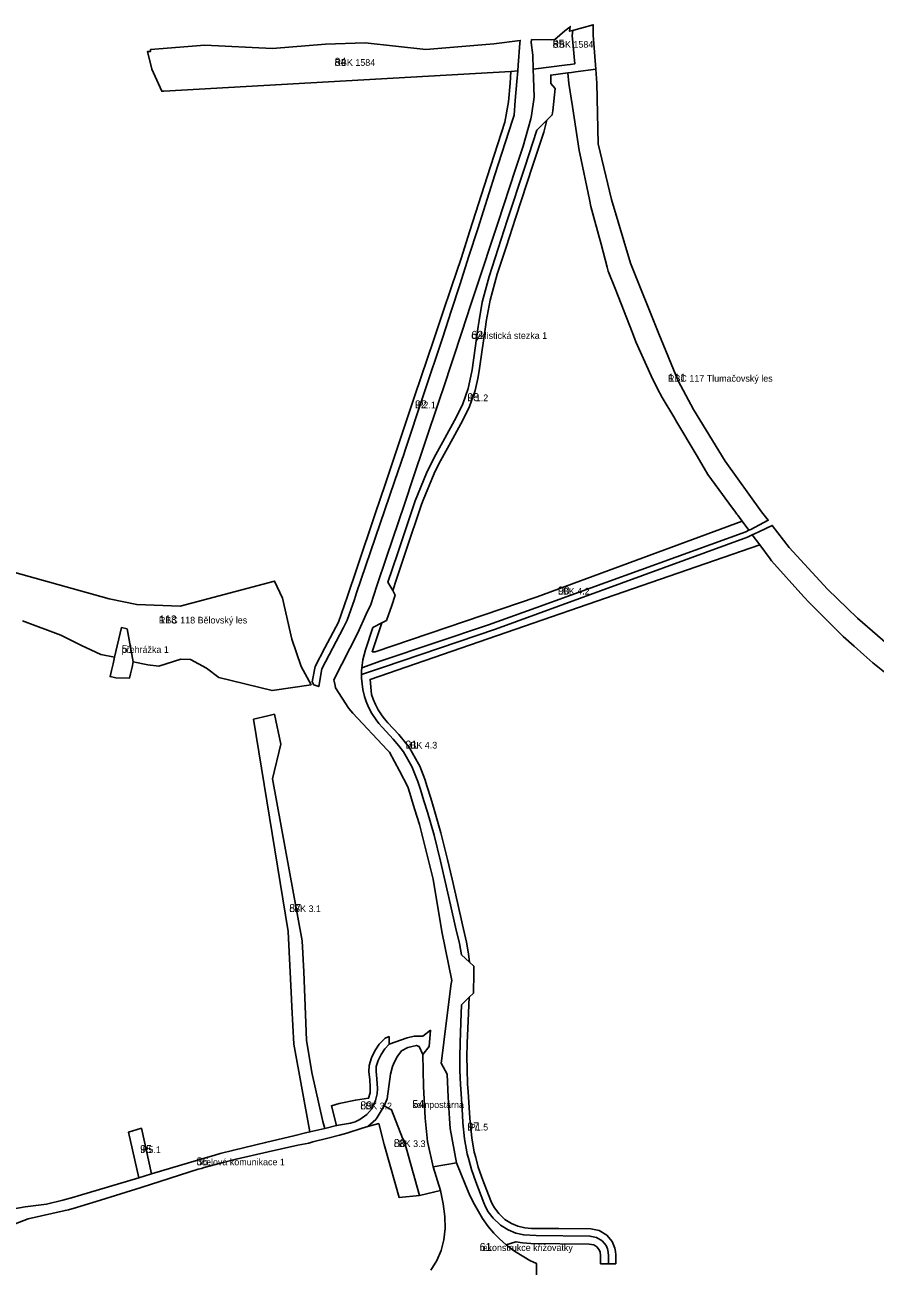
# Model space of a CAD drawing. Extents: x -535270 to -532834, y -1165802 to -1163869.
# Drawn here: x -534261 to -533624, y -1164800 to -1163869 of the extents above; entities that cross this region are included whole.
import ezdxf

# ---------------------------------------------------------------- set-up
doc = ezdxf.new("R2010")
doc.units = 0
for name, color, linetype in [('96120023', 7, 'Continuous'), ('96140023', 7, 'Continuous'), ('ID_VPO', 7, 'Continuous'), ('ID_VPS', 7, 'Continuous')]:
    doc.layers.add(name, color=color, linetype=linetype)

msp = doc.modelspace()

# ---------------------------------------------------------------- linework, layer by layer
at = {"layer": '96120023'}
for points in [[(-533865.57, -1163933.56), (-533865.91, -1163936.5), (-533870.02, -1163940.58), (-533877.5, -1163948), (-533886.52, -1163975.58), (-533899.61, -1164015.61), (-533906.48, -1164036.62), (-533913.28, -1164057.68), (-533918.33, -1164076.95), (-533920.79, -1164090.56), (-533921.44, -1164095.24), (-533925.9, -1164127.57), (-533927.65, -1164135.96), (-533928.81, -1164141.55), (-533932.87, -1164153.05), (-533937.61, -1164162.79), (-533947.95, -1164181.5), (-533954.46, -1164193.28), (-533960.24, -1164204.99), (-533968.74, -1164225.79), (-533982.01, -1164265.49), (-533989.08, -1164286.72), (-533985.51, -1164293.11), (-533983.62, -1164296.49), (-533986.25, -1164304.27), (-533990.03, -1164315.44), (-533993.55, -1164317.25), (-534000.42, -1164320.8), (-534005.96, -1164337.46), (-534007.91, -1164344.99), (-534008.51, -1164350.98), (-534008.75, -1164353.35), (-534008.78, -1164356.1), (-534008.8, -1164358.71), (-534007.78, -1164367.31), (-534006.52, -1164372.41), (-534005.28, -1164376.27), (-534003.55, -1164380.41), (-534001.01, -1164385.28), (-533997.89, -1164390.03), (-533995.93, -1164392.62), (-533993.15, -1164395.78), (-533985.03, -1164404.42), (-533980.98, -1164409.46), (-533977.3, -1164414.04), (-533971.18, -1164424.88), (-533966.53, -1164436.25), (-533964.72, -1164442.12), (-533962.1, -1164450.63), (-533959.46, -1164459.21), (-533954.43, -1164476.51), (-533949.56, -1164496.05), (-533946.1, -1164511.21), (-533942.1, -1164528.74), (-533938.31, -1164545.34), (-533935.48, -1164557.76), (-533933.92, -1164566.17), (-533928.05, -1164571.61), (-533924.63, -1164574.77), (-533924.73, -1164579.85), (-533925.01, -1164594.77), (-533928.18, -1164597.93), (-533933.84, -1164603.58), (-533934.37, -1164616.83), (-533935.02, -1164632.23), (-533935.27, -1164642.87), (-533935.11, -1164652.97), (-533934.7, -1164663.37), (-533934.28, -1164670.15), (-533933.27, -1164686.29), (-533932.91, -1164692.07), (-533931.63, -1164704.16), (-533929.63, -1164715.24), (-533928.48, -1164719.55), (-533926.51, -1164726.96), (-533923.23, -1164736.29), (-533917.13, -1164752.07), (-533915.85, -1164755.07), (-533913.84, -1164758.78), (-533910.07, -1164763.67), (-533904.66, -1164768.75), (-533899.01, -1164772.27), (-533893.29, -1164774.74), (-533887.25, -1164776.17), (-533878.08, -1164776.63), (-533837.66, -1164776.99), (-533832.65, -1164777.97), (-533828.58, -1164780.48), (-533825.63, -1164784), (-533824.52, -1164786.62), (-533824.15, -1164787.49), (-533823.65, -1164791.29), (-533823.66, -1164792.47), (-533823.71, -1164797.74), (-533829.71, -1164797.73), (-533829.65, -1164791.65), (-533829.99, -1164789.08), (-533830.8, -1164787.17), (-533832.55, -1164785.08), (-533834.87, -1164783.65), (-533838.26, -1164782.99), (-533881.99, -1164782.6), (-533888.18, -1164782.11), (-533893.1, -1164781.25), (-533900.4, -1164783.5), (-533905.41, -1164779.1), (-533909.76, -1164774.69), (-533913.99, -1164769.72), (-533918.27, -1164763.7), (-533924.26, -1164753.32), (-533927.76, -1164746.58), (-533931.13, -1164738.19), (-533937.62, -1164722.08), (-533942.48, -1164696.43), (-533942.91, -1164688.74), (-533943.81, -1164672.76), (-533944.79, -1164655.52), (-533949.17, -1164647.34), (-533948.72, -1164643.84), (-533945.61, -1164619.41), (-533941.56, -1164587.64), (-533941.27, -1164585.42), (-533948.58, -1164548.78), (-533951.43, -1164531.95), (-533954.44, -1164514.16), (-533955.24, -1164509.41), (-533962.73, -1164479.54), (-533965.5, -1164468.47), (-533967.42, -1164462.17), (-533970.07, -1164453.5), (-533972.65, -1164445.05), (-533974.15, -1164440.11), (-533980.48, -1164428.25), (-533987.96, -1164414.23), (-533989.65, -1164412.42), (-534015.26, -1164385.02), (-534018.44, -1164381.61), (-534028.41, -1164366.06), (-534028.73, -1164364.37), (-534029.36, -1164361.07), (-534029.56, -1164360.01), (-534011.6, -1164324.7), (-534005.27, -1164310.75), (-534001.99, -1164303.55), (-533997.28, -1164289.55), (-533990.05, -1164268), (-533976.69, -1164228.26), (-533969.8, -1164207.76), (-533961.89, -1164184.21), (-533949.83, -1164148.31), (-533947.71, -1164141.88), (-533933.43, -1164098.59), (-533927.12, -1164079.43), (-533920.66, -1164059.82), (-533916.23, -1164046.38), (-533913.66, -1164038.64), (-533906.69, -1164017.55), (-533893.35, -1163977.24), (-533887.65, -1163959.99), (-533881.92, -1163939.56), (-533881.54, -1163937.07), (-533879.45, -1163923.12), (-533879.91, -1163908.81), (-533880.13, -1163902.18), (-533854.78, -1163899), (-533852.16, -1163898.66), (-533849.07, -1163898.26), (-533850.88, -1163877.07), (-533850.38, -1163873.16), (-533849.75, -1163872.99), (-533835.15, -1163868.99), (-533835.25, -1163876.86), (-533833.31, -1163902.27), (-533848.56, -1163904.24), (-533851.57, -1163904.63), (-533854.21, -1163904.97), (-533867, -1163906.62), (-533867.05, -1163912.94), (-533863.61, -1163916.63)], [(-534192.95, -1164358.6), (-534197.24, -1164357.62), (-534196.17, -1164352.93), (-534195.06, -1164348.06), (-534193.93, -1164343.09), (-534188.86, -1164320.87), (-534184.57, -1164321.84), (-534179.95, -1164346.54), (-534180.86, -1164350.56), (-534181.97, -1164355.44), (-534182.72, -1164358.73)], [(-533976.64, -1164706.23), (-533978.18, -1164703.55), (-533986.32, -1164682.27), (-533991.85, -1164679.44), (-533989.59, -1164674.03), (-533987.09, -1164655.67), (-533985.58, -1164649.89), (-533984.79, -1164648.09), (-533982.7, -1164643.29), (-533981.73, -1164641.88), (-533978.83, -1164638.24), (-533974.09, -1164635.67), (-533967.69, -1164634.08), (-533965.77, -1164634.87), (-533962.79, -1164640.92), (-533962.47, -1164664.91), (-533961.14, -1164688.48), (-533959.32, -1164706.09), (-533955.09, -1164725.13), (-533949.63, -1164742.72), (-533954.82, -1164744.13), (-533965.28, -1164746.51)]]:
    msp.add_lwpolyline(points, close=True, dxfattribs=at)
for points in [[(-534270.96, -1164756.82), (-534260.89, -1164754.96), (-534245.02, -1164753.04), (-534232.71, -1164750.02), (-534224.58, -1164747.89), (-534221.26, -1164746.89), (-534175.74, -1164733.28), (-534166.14, -1164730.4), (-534130.01, -1164719.57), (-534118.87, -1164716.27), (-534114.9, -1164715.1), (-534104.66, -1164712.55), (-534080.73, -1164706.92), (-534058.6, -1164701.5), (-534050.86, -1164699.67), (-534047.57, -1164698.89), (-534036.35, -1164696.24), (-534027.57, -1164694.18), (-534021.63, -1164693.1), (-534017.22, -1164692.32), (-534013.67, -1164691.24), (-534010.02, -1164689.51), (-534004.94, -1164685.91), (-534001.2, -1164681.66), (-533999.6, -1164678), (-533998.47, -1164675.42), (-533997.1, -1164670.37), (-533996.9, -1164666.28), (-533997.34, -1164659.16), (-533997.92, -1164653.73), (-533997.86, -1164649.94), (-533996.38, -1164645.34), (-533994.23, -1164640.86), (-533991.34, -1164636.53), (-533988.12, -1164633.16), (-533974.64, -1164628.33), (-533969.29, -1164627.24), (-533963.01, -1164627.2), (-533957.21, -1164622.74), (-533958.25, -1164634.91), (-533962.79, -1164640.92), (-533965.77, -1164634.87), (-533967.69, -1164634.08), (-533974.09, -1164635.67), (-533978.83, -1164638.24), (-533981.73, -1164641.88), (-533982.7, -1164643.29), (-533984.79, -1164648.09), (-533985.58, -1164649.89), (-533987.09, -1164655.67), (-533989.59, -1164674.03), (-533991.85, -1164679.44), (-533997.19, -1164688.03), (-533998.16, -1164689.6), (-534004.08, -1164694.94), (-534008.47, -1164696.16), (-534019.93, -1164699.91), (-534025.36, -1164701.44), (-534034.2, -1164703.61), (-534045.29, -1164706.38), (-534048.46, -1164707.26), (-534056.65, -1164708.94), (-534078.7, -1164713.71), (-534102.86, -1164719.22), (-534114.47, -1164722.35), (-534126.83, -1164725.69), (-534128.73, -1164726.22), (-534131.26, -1164726.94), (-534174.08, -1164740.65), (-534204.47, -1164750.16), (-534219.28, -1164754.5), (-534222.59, -1164755.48), (-534228.45, -1164757.19), (-534231.06, -1164757.76), (-534258.61, -1164764.08), (-534268.47, -1164767.68)], [(-533956.94, -1164802.51), (-533952.29, -1164795.25), (-533949.05, -1164787.68), (-533947.08, -1164779.74), (-533946.27, -1164771.35), (-533946.51, -1164762.43), (-533947.67, -1164752.92), (-533949.63, -1164742.72), (-533955.09, -1164725.13), (-533937.62, -1164722.08), (-533931.13, -1164738.19), (-533927.76, -1164746.58), (-533924.26, -1164753.32), (-533918.27, -1164763.7), (-533913.99, -1164769.72), (-533909.76, -1164774.69), (-533905.41, -1164779.1), (-533900.4, -1164783.5), (-533894.97, -1164787.72), (-533893.07, -1164788.97), (-533882.67, -1164795.39), (-533877.62, -1164797.66), (-533877.61, -1164812.17)]]:
    msp.add_lwpolyline(points, dxfattribs=at)
at = {"layer": '96140023'}
for points in [[(-533854.78, -1163899), (-533880.13, -1163902.18), (-533880.47, -1163891.74), (-533881.62, -1163882.25), (-533881.4, -1163880.05), (-533866.68, -1163880.24), (-533863.98, -1163879.91), (-533856.45, -1163873.6), (-533853.53, -1163871.16), (-533852.38, -1163870.19), (-533852.91, -1163873.85), (-533850.38, -1163873.16), (-533850.88, -1163877.07), (-533849.07, -1163898.26), (-533852.16, -1163898.66)], [(-533896.86, -1163903.88), (-534157.03, -1163918.7), (-534158.61, -1163918.79), (-534166.07, -1163902.27), (-534169.16, -1163888.95), (-534166.94, -1163888.88), (-534167.05, -1163887.54), (-534126.29, -1163884.14), (-534075.55, -1163886.63), (-534035.93, -1163883.59), (-534006.23, -1163882.44), (-533960.63, -1163887.47), (-533909.61, -1163883.3), (-533889.94, -1163880.68), (-533890.12, -1163882.84), (-533891.45, -1163899.11), (-533891.82, -1163903.6)], [(-534019.39, -1164297.19), (-534012.47, -1164276.63), (-533998.41, -1164234.88), (-533991.22, -1164213.52), (-533983.93, -1164191.87), (-533969.04, -1164147.65), (-533954.68, -1164105), (-533948.09, -1164085.43), (-533941.36, -1164065.45), (-533934.17, -1164044.09), (-533927.58, -1164023.51), (-533914.6, -1163983), (-533901.42, -1163941.85), (-533898.72, -1163926.84), (-533897.57, -1163912.61), (-533896.86, -1163903.88), (-533891.82, -1163903.6), (-533892.46, -1163911.51), (-533893.61, -1163925.64), (-533894.49, -1163936.59), (-533895.7, -1163940.37), (-533908.87, -1163981.51), (-533921.81, -1164021.92), (-533928.41, -1164042.51), (-533935.24, -1164063.87), (-533941.57, -1164083.63), (-533941.6, -1164083.7), (-533947.99, -1164103.02), (-533962.05, -1164145.52), (-533976.56, -1164189.37), (-533976.67, -1164189.68), (-533984.05, -1164211.29), (-533991.32, -1164232.59), (-534005.58, -1164274.33), (-534012.59, -1164294.86), (-534014.24, -1164299.69), (-534019.56, -1164315.28), (-534022.34, -1164320.65), (-534038.5, -1164351.85), (-534040.96, -1164365.04), (-534044.64, -1164363.71), (-534045.79, -1164361.5), (-534043.66, -1164350.07), (-534036.35, -1164335.95), (-534026.03, -1164316.9)], [(-533723.64, -1164241.09), (-533723.64, -1164241.09), (-533725.58, -1164238.43), (-533726.88, -1164236.66), (-533727.58, -1164235.7), (-533728.64, -1164234.23), (-533733.55, -1164227.5), (-533740.96, -1164217.33), (-533749.2, -1164206.03), (-533750.29, -1164204.21), (-533758.05, -1164191.21), (-533772.63, -1164166.78), (-533774.86, -1164162.96), (-533783.44, -1164148.24), (-533787.38, -1164141.47), (-533791.66, -1164132.02), (-533803.18, -1164106.57), (-533805.75, -1164099.98), (-533818.83, -1164066.55), (-533823.91, -1164053.54), (-533824.72, -1164050.56), (-533829.37, -1164033.3), (-533833.99, -1164016.17), (-533836.92, -1164005.27), (-533838.01, -1164000.05), (-533845.21, -1163965.55), (-533845.71, -1163963.15), (-533850.77, -1163930.31), (-533853.43, -1163913.02), (-533854.21, -1163904.97), (-533851.57, -1163904.63), (-533848.56, -1163904.24), (-533833.31, -1163902.27), (-533832.51, -1163912.75), (-533831.47, -1163958.19), (-533821.43, -1163999.88), (-533807.37, -1164047.78), (-533785.98, -1164100.6), (-533771.58, -1164135.97), (-533760.11, -1164157.23), (-533736.29, -1164196.18), (-533708.99, -1164234.05), (-533704.04, -1164240.43), (-533713.81, -1164245.46), (-533717.2, -1164247.2), (-533718.6, -1164247.92)], [(-533880.35, -1163974.08), (-533893.37, -1164013.89), (-533900.22, -1164034.85), (-533907.1, -1164055.88), (-533912.46, -1164075.3), (-533915.46, -1164091.41), (-533915.77, -1164093.65), (-533920.57, -1164128.49), (-533921.77, -1164134.22), (-533923.6, -1164143.01), (-533927.88, -1164155.13), (-533932.82, -1164165.28), (-533940.47, -1164179.13), (-533949.69, -1164195.81), (-533953.36, -1164203), (-533954.52, -1164205.26), (-533962.74, -1164225.38), (-533964.01, -1164228.51), (-533975.66, -1164263.5), (-533982.65, -1164284.5), (-533985.51, -1164293.11), (-533989.08, -1164286.72), (-533982.01, -1164265.49), (-533968.74, -1164225.79), (-533960.24, -1164204.99), (-533954.46, -1164193.28), (-533947.95, -1164181.5), (-533937.61, -1164162.79), (-533932.87, -1164153.05), (-533928.81, -1164141.55), (-533927.65, -1164135.96), (-533925.9, -1164127.57), (-533921.44, -1164095.24), (-533920.79, -1164090.56), (-533918.33, -1164076.95), (-533913.28, -1164057.68), (-533906.48, -1164036.62), (-533899.61, -1164015.61), (-533886.52, -1163975.58), (-533877.5, -1163948), (-533870.02, -1163940.58), (-533872.31, -1163949.52)], [(-534005.96, -1164337.46), (-534000.42, -1164320.8), (-533993.55, -1164317.25), (-534000.78, -1164338.99), (-533998.54, -1164338.94), (-533877.27, -1164297.75), (-533723.64, -1164241.09), (-533718.6, -1164247.92), (-533720.89, -1164249.1), (-533878.29, -1164305.99), (-533913.76, -1164318.81), (-533994.16, -1164345.79), (-534008.51, -1164350.98), (-534007.91, -1164344.99)], [(-533954.44, -1164476.5), (-533959.46, -1164459.21), (-533962.1, -1164450.63), (-533964.72, -1164442.12), (-533966.53, -1164436.25), (-533971.18, -1164424.88), (-533977.3, -1164414.04), (-533980.98, -1164409.46), (-533985.03, -1164404.42), (-533993.15, -1164395.78), (-533995.93, -1164392.62), (-533997.89, -1164390.03), (-534001.01, -1164385.28), (-534003.55, -1164380.41), (-534005.28, -1164376.27), (-534006.52, -1164372.41), (-534007.78, -1164367.31), (-534008.8, -1164358.71), (-534008.78, -1164356.1), (-533992.49, -1164350.51), (-533908.35, -1164322), (-533719.5, -1164253.06), (-533716, -1164251.39), (-533710.42, -1164258.88), (-534002.49, -1164359.73), (-534001.32, -1164370.93), (-534000.21, -1164374.4), (-533998.5, -1164378.42), (-533996.35, -1164382.54), (-533993.47, -1164386.92), (-533991.74, -1164389.2), (-533989.15, -1164392.15), (-533980.95, -1164400.87), (-533975.54, -1164407.6), (-533972.81, -1164411), (-533966.03, -1164423.02), (-533965.13, -1164424.63), (-533961.41, -1164434.5), (-533959.65, -1164440.24), (-533957.01, -1164448.81), (-533954.39, -1164457.32), (-533949.35, -1164474.63), (-533944.31, -1164494.8), (-533940.98, -1164509.39), (-533936.96, -1164526.97), (-533933.17, -1164543.61), (-533930.19, -1164556.66), (-533928.57, -1164565.45), (-533928.05, -1164571.61), (-533933.92, -1164566.17), (-533935.48, -1164557.76), (-533938.31, -1164545.34), (-533942.1, -1164528.74), (-533946.1, -1164511.21), (-533949.56, -1164496.05), (-533954.43, -1164476.51)], [(-534059.7, -1164633.02), (-534061.1, -1164605.06), (-534061.38, -1164599.3), (-534063.91, -1164548.66), (-534089.79, -1164389.61), (-534079.02, -1164386.99), (-534074.12, -1164385.79), (-534069.21, -1164408.2), (-534075.64, -1164434.19), (-534053.31, -1164555.72), (-534052.06, -1164578.82), (-534050.05, -1164630.03), (-534046.04, -1164654.24), (-534037.87, -1164691), (-534036.35, -1164696.24), (-534047.57, -1164698.89)], [(-533929.62, -1164632.41), (-533929.87, -1164642.89), (-533929.73, -1164651.56), (-533929.31, -1164663.09), (-533928.96, -1164668.69), (-533927.94, -1164684.93), (-533927.52, -1164691.62), (-533926.28, -1164703.39), (-533924.36, -1164714.06), (-533923.28, -1164718.12), (-533921.34, -1164725.36), (-533917.93, -1164735.02), (-533911.85, -1164750.68), (-533910.98, -1164752.72), (-533909.3, -1164755.82), (-533906.06, -1164760.03), (-533901.35, -1164764.45), (-533896.5, -1164767.48), (-533891.59, -1164769.6), (-533886.42, -1164770.81), (-533881.49, -1164771.2), (-533861.01, -1164771.38), (-533837.11, -1164771.6), (-533830.66, -1164772.85), (-533825, -1164776.34), (-533820.97, -1164781.15), (-533818.89, -1164786.06), (-533818.58, -1164788.43), (-533818.25, -1164790.97), (-533818.28, -1164794.08), (-533818.31, -1164797.76), (-533820.59, -1164797.75), (-533823.21, -1164797.74), (-533823.71, -1164797.74), (-533823.66, -1164792.47), (-533823.65, -1164791.29), (-533824.15, -1164787.49), (-533824.52, -1164786.62), (-533825.63, -1164784), (-533828.58, -1164780.48), (-533832.65, -1164777.97), (-533837.66, -1164776.99), (-533878.08, -1164776.63), (-533887.25, -1164776.17), (-533893.29, -1164774.74), (-533899.01, -1164772.27), (-533904.66, -1164768.75), (-533910.07, -1164763.67), (-533913.84, -1164758.78), (-533915.85, -1164755.07), (-533917.13, -1164752.07), (-533923.23, -1164736.29), (-533926.51, -1164726.96), (-533928.48, -1164719.55), (-533929.63, -1164715.24), (-533931.63, -1164704.16), (-533932.91, -1164692.07), (-533933.27, -1164686.29), (-533934.28, -1164670.15), (-533934.7, -1164663.37), (-533935.11, -1164652.97), (-533935.27, -1164642.87), (-533935.02, -1164632.23), (-533934.37, -1164616.83), (-533933.84, -1164603.58), (-533928.18, -1164597.93), (-533928.92, -1164615.57)], [(-534002.47, -1164669.52), (-534002.31, -1164666.32), (-534002.38, -1164665.12), (-534002.72, -1164659.61), (-534003.32, -1164653.97), (-534003.25, -1164649.05), (-534001.41, -1164643.34), (-533998.93, -1164638.18), (-533995.57, -1164633.14), (-533991.14, -1164628.51), (-533988.22, -1164627.46), (-533988.12, -1164633.16), (-533991.34, -1164636.53), (-533994.23, -1164640.86), (-533996.38, -1164645.34), (-533997.86, -1164649.94), (-533997.92, -1164653.73), (-533997.34, -1164659.16), (-533996.9, -1164666.28), (-533997.1, -1164670.37), (-533998.47, -1164675.42), (-533999.6, -1164678), (-534001.2, -1164681.66), (-534004.94, -1164685.91), (-534010.02, -1164689.51), (-534013.67, -1164691.24), (-534017.22, -1164692.32), (-534021.63, -1164693.1), (-534027.57, -1164694.18), (-534031.42, -1164679.27), (-534025.51, -1164677.62), (-534013.38, -1164675.05), (-534003.58, -1164673.62)], [(-533998.16, -1164689.6), (-533997.19, -1164688.03), (-533991.85, -1164679.44), (-533986.32, -1164682.27), (-533978.18, -1164703.55), (-533976.64, -1164706.23), (-533965.28, -1164746.51), (-533980.66, -1164747.97), (-533983.41, -1164738.37), (-533992.01, -1164708.4), (-533996, -1164692.7), (-534004.08, -1164694.94)], [(-534166.14, -1164730.4), (-534175.74, -1164733.28), (-534183.46, -1164699.06), (-534173.86, -1164696.18)]]:
    msp.add_lwpolyline(points, close=True, dxfattribs=at)
for points in [[(-533616.81, -1164354.28), (-533625.55, -1164347.3), (-533632.43, -1164341.14), (-533639.6, -1164334.73), (-533647.79, -1164327.4), (-533662.64, -1164312.76), (-533673.2, -1164302.34), (-533677.32, -1164297.76), (-533701.48, -1164270.84), (-533702.69, -1164269.23), (-533710.42, -1164258.88), (-533716, -1164251.39), (-533714.4, -1164250.63), (-533710.99, -1164249), (-533701.07, -1164244.26), (-533688.28, -1164260.76), (-533659.7, -1164292.03), (-533637.12, -1164313.74), (-533614.65, -1164333.34)], [(-534274.99, -1164277.69), (-534197.87, -1164299.21), (-534177.29, -1164303.6), (-534144.82, -1164304.74), (-534074.04, -1164285.93), (-534068.03, -1164298.87), (-534061.1, -1164329.42), (-534054.06, -1164350.04), (-534046.67, -1164363.75), (-534075.84, -1164368.05), (-534115.69, -1164358.28), (-534124.97, -1164351.29), (-534136.93, -1164344.68), (-534144.37, -1164344.48), (-534160.64, -1164349.81), (-534168.89, -1164348.83), (-534179.95, -1164346.54), (-534184.57, -1164321.84), (-534188.86, -1164320.87), (-534193.93, -1164343.09), (-534204.16, -1164340.9), (-534218.68, -1164334.39), (-534234.12, -1164326.63), (-534262.91, -1164315.76)]]:
    msp.add_lwpolyline(points, dxfattribs=at)

# ---------------------------------------------------------------- texts
at = {"layer": '96120023'}
for s, rotation, p in [('cyklistická stezka 1', 0, (-533926.6, -1164104.42)), ('přehrážka 1', 0, (-534188.59, -1164339.79)), ('kompostárna', 0, (-533970.74, -1164680.99)), ('účelová komunikace 1', 360, (-534132.46, -1164723.94))]:
    msp.add_text(s, height=5, rotation=rotation, dxfattribs=at).set_placement(p)
msp.add_text('rekonstrukce křižovatky', height=5, dxfattribs=at).set_placement((-533920.36, -1164788.14))
at = {"layer": '96140023'}
for s, rotation, p in [('RBK 1584', 360, (-533865.62, -1163886.18)), ('RBK 1584', 360, (-534029.08, -1163899.73)), ('RBC 117 Tlumačovský les', 0, (-533779.12, -1164136.54)), ('IP1.2', 0, (-533929.55, -1164151.11)), ('IP2.1', 360, (-533968.8, -1164156.44)), ('LBK 4.2', 0, (-533861.69, -1164296.04)), ('RBC 118 Bělovský les', 0, (-534160.69, -1164317.75)), ('LBK 4.3', 0, (-533975.93, -1164411.5)), ('LBK 3.1', 360, (-534063.07, -1164534.06)), ('LBK 3.2', 0, (-534009.77, -1164681.93)), ('IP1.5', 360, (-533929.58, -1164697.84)), ('LBK 3.3', 0, (-533984.68, -1164710.25)), ('IP5.1', 360, (-534174.8, -1164714.73))]:
    msp.add_text(s, height=5, rotation=rotation, dxfattribs=at).set_placement(p)
at = {"layer": 'ID_VPO'}
for s, rotation, p in [('85', 360, (-533865.62, -1163886.18)), ('84', 0, (-534029.08, -1163899.73)), ('111', 0, (-533779.12, -1164136.54)), ('93', 360, (-533929.55, -1164151.11)), ('92', 0, (-533968.8, -1164156.44)), ('90', 0, (-533861.69, -1164296.04)), ('113', 0, (-534160.69, -1164317.75)), ('91', 360, (-533975.93, -1164411.5)), ('87', 0, (-534063.07, -1164534.06)), ('89', 0, (-534009.77, -1164681.93)), ('97', 360, (-533929.58, -1164697.84)), ('88', 0, (-533984.68, -1164710.25)), ('95', 360, (-534174.8, -1164714.73))]:
    msp.add_text(s, height=6, rotation=rotation, dxfattribs=at).set_placement(p)
at = {"layer": 'ID_VPS'}
for s, rotation, p in [('62', 0, (-533926.6, -1164104.42)), ('51', 360, (-534188.59, -1164339.79)), ('54', 360, (-533970.74, -1164680.99)), ('36', 360, (-534132.46, -1164723.94)), ('61', 360, (-533920.36, -1164788.14))]:
    msp.add_text(s, height=6, rotation=rotation, dxfattribs=at).set_placement(p)

doc.saveas('drawing.dxf')
